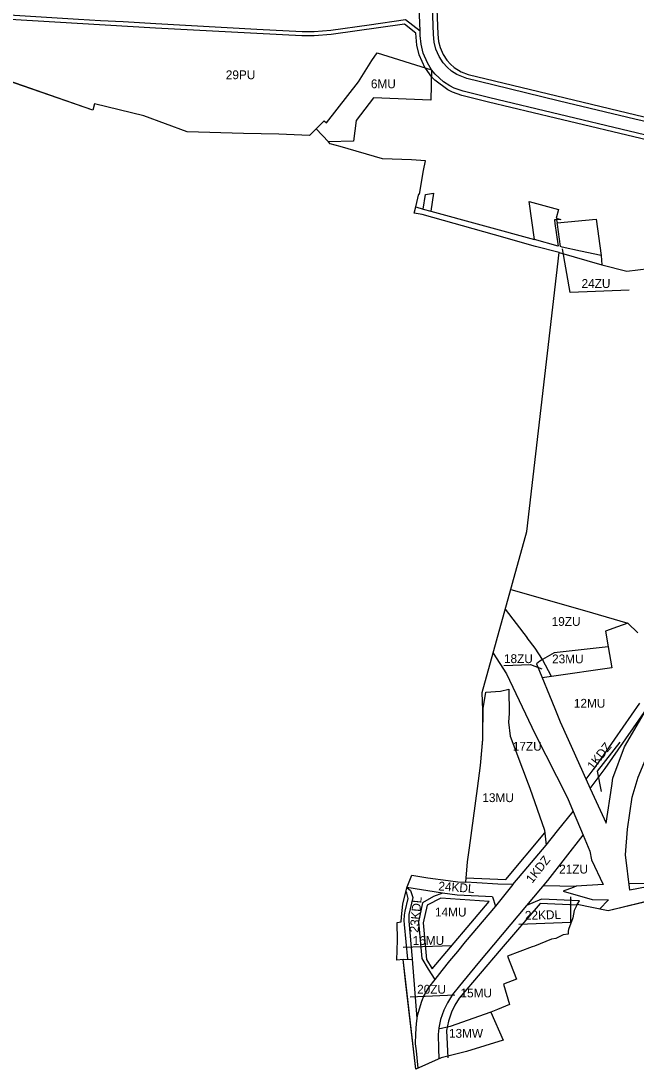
# Model space of a CAD drawing. Extents: x 7428203 to 7432868, y 5542672 to 5545406.
# Drawn here: x 7429895 to 7430591, y 5542672 to 5543859 of the extents above; entities that cross this region are included whole.
import ezdxf

# ---------------------------------------------------------------- set-up
doc = ezdxf.new("R2010")
doc.units = 0
for name, color, linetype in [('granica_planu', 7, 'Continuous'), ('linie_rozgraniczajace', 7, 'Continuous'), ('linie_zabudowy_nieprzekraczalne', 7, 'Continuous'), ('oznaczenia_przeznaczen', 7, 'Continuous')]:
    doc.layers.add(name, color=color, linetype=linetype)

msp = doc.modelspace()

# ---------------------------------------------------------------- linework, layer by layer
at = {"layer": 'granica_planu'}
for points in [[(7430399.26, 5542692.02), (7430370.61, 5542685.08), (7430341.91, 5542672.31), (7430330.7, 5542768.67), (7430330.7, 5542768.67), (7430327.49, 5542796.26), (7430320.3, 5542795.69), (7430321.05, 5542818.01), (7430320.88, 5542838.31), (7430325.25, 5542838.8), (7430325.66, 5542844.48), (7430327.19, 5542858.94), (7430328.79, 5542865.49), (7430332.01, 5542878.54), (7430337.22, 5542891.81), (7430355.36, 5542888.75), (7430378.35, 5542885.67), (7430389.37, 5542884.14), (7430398.44, 5542883.87), (7430400.23, 5542906.78), (7430402.42, 5542922.52), (7430411.79, 5542990), (7430415.17, 5543015.97), (7430417.67, 5543045.72), (7430417.86, 5543078.34), (7430416.94, 5543098.58), (7430467.52, 5543280.84), (7430504.08, 5543596.71), (7430477.25, 5543603.35), (7430430.7, 5543616.56), (7430348.97, 5543639.53), (7430340.06, 5543641.03), (7430341.69, 5543648.06), (7430345.12, 5543662.83), (7430346.18, 5543662.73), (7430350.57, 5543689.27), (7430352.87, 5543700.45), (7430336.88, 5543701.56), (7430304.26, 5543702.62), (7430256.11, 5543716.51), (7430245, 5543719.71), (7430243.12, 5543721.71), (7430229.11, 5543736.52), (7430221.53, 5543728.89), (7430186.76, 5543730.38), (7430146.86, 5543731.42), (7430083.21, 5543733.08), (7430033.89, 5543751.38), (7429978.34, 5543764.67), (7429976.28, 5543757.53), (7429864.43, 5543796.42)], [(7430647.46, 5542872.71), (7430559.44, 5542851.36), (7430524.39, 5542858.43), (7430520.91, 5542851.84), (7430519.38, 5542843.51), (7430514.61, 5542830.08), (7430514.44, 5542828.34), (7430514.29, 5542824.95), (7430508.52, 5542824.11), (7430500.18, 5542819.96), (7430495.44, 5542819.32), (7430476.16, 5542811.39), (7430473.47, 5542810.47), (7430445.63, 5542800.07), (7430455.63, 5542773.98), (7430441.2, 5542768.33), (7430447.71, 5542745.36), (7430434.45, 5542739.61), (7430426.73, 5542736.58), (7430440.59, 5542705.03), (7430399.26, 5542692.02)]]:
    msp.add_lwpolyline(points, dxfattribs=at)
at = {"layer": 'linie_rozgraniczajace'}
for p, q in [((7430361.88, 5543843.19), (7430359.23, 5543909.49)), ((7430346.91, 5543842.24), (7430346.69, 5543847.34)), ((7430347.76, 5543832.24), (7430346.91, 5543842.24)), ((7430362.6, 5543834.7), (7430361.88, 5543843.19)), ((7430350.31, 5543822), (7430347.76, 5543832.24)), ((7430364.56, 5543826.82), (7430362.6, 5543834.7)), ((7430368.19, 5543818.43), (7430364.56, 5543826.82)), ((7430276.96, 5543789.82), (7430292.1, 5543813.97)), ((7430292.1, 5543813.97), (7430298.18, 5543822.67)), ((7430298.18, 5543822.67), (7430359.58, 5543803.14)), ((7430354.93, 5543811.31), (7430350.31, 5543822)), ((7430372.8, 5543811.34), (7430368.19, 5543818.43)), ((7430359.58, 5543803.14), (7430354.93, 5543811.31)), ((7430359.58, 5543803.14), (7430358.92, 5543768.83)), ((7430363.63, 5543798.4), (7430359.58, 5543803.14)), ((7430377.38, 5543806.15), (7430372.8, 5543811.34)), ((7430382.32, 5543801.82), (7430377.38, 5543806.15)), ((7430388.18, 5543797.9), (7430382.32, 5543801.82)), ((7429976.28, 5543757.53), (7429864.43, 5543796.42)), ((7430240.89, 5543743.17), (7430276.96, 5543789.82)), ((7430373.17, 5543789.9), (7430363.63, 5543798.4)), ((7430380.46, 5543785.02), (7430373.17, 5543789.9)), ((7430399.68, 5543793.4), (7430388.18, 5543797.9)), ((7430429, 5543786.28), (7430399.68, 5543793.4)), ((7430385.17, 5543782.5), (7430380.46, 5543785.02)), ((7430395.48, 5543778.99), (7430385.17, 5543782.5)), ((7430425.46, 5543771.7), (7430395.48, 5543778.99)), ((7430504.48, 5543767.95), (7430429, 5543786.28)), ((7430293.83, 5543771.61), (7430274.43, 5543745.9)), ((7430358.92, 5543768.83), (7430293.83, 5543771.61)), ((7430583.41, 5543733.76), (7430425.46, 5543771.7)), ((7430589.68, 5543747.58), (7430504.48, 5543767.95)), ((7429978.34, 5543764.67), (7429976.28, 5543757.53)), ((7430033.89, 5543751.38), (7429978.34, 5543764.67)), ((7430083.21, 5543733.08), (7430033.89, 5543751.38)), ((7430229.11, 5543736.52), (7430238.02, 5543745.75)), ((7430238.02, 5543745.75), (7430240.89, 5543743.17)), ((7430274.43, 5543745.9), (7430271.19, 5543722.58)), ((7430715.18, 5543717.91), (7430589.68, 5543747.58)), ((7430146.86, 5543731.42), (7430083.21, 5543733.08)), ((7430186.76, 5543730.38), (7430146.86, 5543731.42)), ((7430221.53, 5543728.89), (7430186.76, 5543730.38)), ((7430229.11, 5543736.52), (7430221.53, 5543728.89)), ((7430243.12, 5543721.71), (7430229.11, 5543736.52)), ((7430710.02, 5543703.71), (7430583.41, 5543733.76)), ((7430271.19, 5543722.58), (7430243.12, 5543721.71)), ((7430245, 5543719.71), (7430243.12, 5543721.71)), ((7430256.11, 5543716.51), (7430245, 5543719.71)), ((7430304.26, 5543702.62), (7430256.11, 5543716.51)), ((7430336.88, 5543701.56), (7430304.26, 5543702.62)), ((7430352.87, 5543700.45), (7430336.88, 5543701.56)), ((7430350.57, 5543689.27), (7430352.87, 5543700.45)), ((7430346.18, 5543662.73), (7430350.57, 5543689.27)), ((7430341.69, 5543648.06), (7430345.12, 5543662.83)), ((7430345.12, 5543662.83), (7430346.18, 5543662.73)), ((7430340.06, 5543641.03), (7430341.69, 5543648.06)), ((7430341.69, 5543648.06), (7430350.15, 5543645.75)), ((7430476.18, 5543611.37), (7430470.01, 5543654.15)), ((7430470.01, 5543654.15), (7430503.27, 5543645.23)), ((7430348.97, 5543639.53), (7430340.06, 5543641.03)), ((7430430.7, 5543616.56), (7430348.97, 5543639.53)), ((7430350.15, 5543645.75), (7430358.87, 5543643.37)), ((7430358.87, 5543643.37), (7430476.18, 5543611.37)), ((7430503.27, 5543645.23), (7430500.82, 5543635.29)), ((7430500.82, 5543635.29), (7430505.8, 5543634)), ((7430505.8, 5543634), (7430501.2, 5543633.57)), ((7430501.2, 5543633.57), (7430501.96, 5543630.19)), ((7430501.96, 5543630.19), (7430545.85, 5543634.39)), ((7430545.85, 5543634.39), (7430551.46, 5543593.14)), ((7430477.25, 5543603.35), (7430430.7, 5543616.56)), ((7430504.08, 5543596.71), (7430477.25, 5543603.35)), ((7430467.52, 5543280.84), (7430504.08, 5543596.71)), ((7430504.08, 5543596.71), (7430552.28, 5543582.65)), ((7430551.46, 5543593.14), (7430552.28, 5543582.65)), ((7430580.6, 5543575.31), (7430686.19, 5543588.57)), ((7430552.28, 5543582.65), (7430580.6, 5543575.31)), ((7430416.94, 5543098.58), (7430467.52, 5543280.84)), ((7430449.28, 5543215.14), (7430532.69, 5543191.3)), ((7430443.12, 5543192.94), (7430467.68, 5543160.5)), ((7430569.97, 5543172.7), (7430556.39, 5543168.05)), ((7430581.89, 5543176.93), (7430569.97, 5543172.7)), ((7430556.39, 5543168.05), (7430559.49, 5543150.31)), ((7430559.53, 5543150.09), (7430498.37, 5543143.44)), ((7430429.27, 5543143.02), (7430444.56, 5543119.7)), ((7430498.37, 5543143.44), (7430485.23, 5543135.92)), ((7430482.22, 5543133.91), (7430478.48, 5543130.78)), ((7430478.48, 5543130.78), (7430499, 5543080.49)), ((7430485.23, 5543135.92), (7430482.22, 5543133.91)), ((7430495.56, 5543116.62), (7430485.26, 5543135.94)), ((7430444.56, 5543119.7), (7430476.37, 5543051.93)), ((7430495.53, 5543116.68), (7430484.82, 5543115.23)), ((7430417.86, 5543078.34), (7430416.94, 5543098.58)), ((7430417.69, 5543048.28), (7430417.86, 5543078.34)), ((7430499, 5543080.49), (7430505.15, 5543065.27)), ((7430505.15, 5543065.27), (7430514.17, 5543045.49)), ((7430415.17, 5543015.97), (7430417.63, 5543045.29)), ((7430448.69, 5543048.95), (7430469.17, 5542994.97)), ((7430476.37, 5543051.93), (7430513.64, 5542979.39)), ((7430514.17, 5543045.49), (7430539.24, 5542989.88)), ((7430411.79, 5542990), (7430415.17, 5543015.97)), ((7430402.42, 5542922.52), (7430411.79, 5542990)), ((7430513.64, 5542979.39), (7430520.07, 5542963.85)), ((7430520.07, 5542963.85), (7430531.21, 5542936.92)), ((7430487.47, 5542942.72), (7430489.31, 5542925.85)), ((7430400.23, 5542906.78), (7430402.42, 5542922.52)), ((7430398.44, 5542883.87), (7430400.23, 5542906.78)), ((7430332.01, 5542878.54), (7430337.22, 5542891.81)), ((7430337.22, 5542891.81), (7430355.36, 5542888.75)), ((7430355.36, 5542888.75), (7430378.35, 5542885.67)), ((7430328.79, 5542865.49), (7430332.01, 5542878.54)), ((7430378.35, 5542885.67), (7430389.37, 5542884.14)), ((7430389.37, 5542884.14), (7430398.44, 5542883.87)), ((7430410.98, 5542883.06), (7430398.44, 5542883.87)), ((7430434.66, 5542881.49), (7430410.98, 5542883.06)), ((7430451.8, 5542881.03), (7430431.89, 5542856.63)), ((7430451.8, 5542881.03), (7430434.66, 5542881.49)), ((7430486.43, 5542880.04), (7430523.21, 5542879.23)), ((7430327.19, 5542858.94), (7430328.79, 5542865.49)), ((7430361.86, 5542867.63), (7430349.22, 5542860.32)), ((7430372.11, 5542871.52), (7430361.86, 5542867.63)), ((7430388.67, 5542869.16), (7430372.11, 5542871.52)), ((7430428.81, 5542867.27), (7430388.67, 5542869.16)), ((7430527.12, 5542862.62), (7430483.9, 5542864.56)), ((7430647.46, 5542872.71), (7430559.44, 5542851.36)), ((7430325.66, 5542844.48), (7430327.19, 5542858.94)), ((7430349.22, 5542860.32), (7430345.03, 5542839.07)), ((7430524.39, 5542858.43), (7430520.91, 5542851.84)), ((7430524.39, 5542858.43), (7430527.12, 5542862.62)), ((7430559.44, 5542851.36), (7430524.39, 5542858.43)), ((7430325.25, 5542838.8), (7430325.66, 5542844.48)), ((7430519.38, 5542843.51), (7430514.61, 5542830.08)), ((7430520.91, 5542851.84), (7430519.38, 5542843.51)), ((7430320.88, 5542838.31), (7430325.25, 5542838.8)), ((7430321.05, 5542818.01), (7430320.88, 5542838.31)), ((7430345.03, 5542839.07), (7430348.61, 5542797.56)), ((7430514.61, 5542830.08), (7430514.44, 5542828.34)), ((7430320.3, 5542795.69), (7430321.05, 5542818.01)), ((7430495.44, 5542819.32), (7430476.16, 5542811.39)), ((7430500.18, 5542819.96), (7430495.44, 5542819.32)), ((7430508.52, 5542824.11), (7430500.18, 5542819.96)), ((7430514.29, 5542824.95), (7430508.52, 5542824.11)), ((7430514.44, 5542828.34), (7430514.29, 5542824.95)), ((7430473.47, 5542810.47), (7430445.63, 5542800.07)), ((7430476.16, 5542811.39), (7430473.47, 5542810.47)), ((7430327.49, 5542796.26), (7430320.3, 5542795.69)), ((7430327.49, 5542796.26), (7430337.69, 5542796.76)), ((7430330.47, 5542770.65), (7430327.49, 5542796.26)), ((7430337.69, 5542796.76), (7430342.98, 5542729.42)), ((7430348.61, 5542797.56), (7430355.92, 5542785.42)), ((7430445.63, 5542800.07), (7430455.63, 5542773.98)), ((7430355.92, 5542785.42), (7430363.19, 5542773.55)), ((7430341.91, 5542672.31), (7430330.47, 5542770.65)), ((7430455.63, 5542773.98), (7430441.2, 5542768.33)), ((7430441.2, 5542768.33), (7430447.71, 5542745.36)), ((7430434.45, 5542739.61), (7430426.73, 5542736.58)), ((7430426.73, 5542736.58), (7430440.59, 5542705.03)), ((7430447.71, 5542745.36), (7430434.45, 5542739.61)), ((7430440.59, 5542705.03), (7430399.26, 5542692.02)), ((7430342.34, 5542692.78), (7430344.11, 5542673.29)), ((7430367.45, 5542695.57), (7430368.03, 5542683.93)), ((7430399.26, 5542692.02), (7430370.61, 5542685.08)), ((7430370.61, 5542685.08), (7430341.91, 5542672.31))]:
    msp.add_line(p, q, dxfattribs=at)
for points in [[(7429692.68, 5543891.06), (7429733.68, 5543881.76), (7429787.12, 5543873.02), (7429851.1, 5543867.29), (7429960.09, 5543860.73), (7429984.9, 5543859.31), (7430010.49, 5543857.85), (7430047.45, 5543855.75), (7430162.05, 5543849.26), (7430213.06, 5543846.63), (7430226.75, 5543846.71), (7430245.5, 5543848.19), (7430288.91, 5543854.44), (7430330.3, 5543860.39), (7430346.69, 5543847.34), (7430344.79, 5543892.69)], [(7430350.15, 5543645.75), (7430352.89, 5543662.25), (7430361.91, 5543663.73), (7430358.87, 5543643.37)], [(7430501.2, 5543633.57), (7430498.67, 5543633.41), (7430498.99, 5543629.46), (7430502.95, 5543603.85), (7430476.18, 5543611.37)], [(7430551.46, 5543593.14), (7430528.07, 5543598.17), (7430507.44, 5543602.61), (7430505.43, 5543603.17), (7430502.22, 5543628.07), (7430501.96, 5543630.19)], [(7430532.69, 5543191.3), (7430581.89, 5543176.93), (7430593.17, 5543166.03)], [(7430485.23, 5543135.92), (7430477.03, 5543148.51), (7430467.68, 5543160.5)], [(7430559.49, 5543150.31), (7430563.82, 5543126.34), (7430495.56, 5543116.62)], [(7430417.63, 5543045.29), (7430417.69, 5543048.28), (7430418.24, 5543080.69), (7430419.99, 5543091.55), (7430421.2, 5543099.06), (7430437.63, 5543100.02), (7430447.03, 5543102.19), (7430447.64, 5543074.71)], [(7430539.24, 5542989.88), (7430556.31, 5543012.63), (7430602.9, 5543079.56)], [(7430539.24, 5542989.88), (7430557.16, 5542950.48), (7430563.6, 5542992.83), (7430564.95, 5543001.72), (7430577.95, 5543036.88), (7430602.9, 5543079.56)], [(7430447.64, 5543074.71), (7430446.92, 5543064.79), (7430448.69, 5543048.95)], [(7430469.17, 5542994.97), (7430470.88, 5542990.09), (7430487.47, 5542942.72)], [(7430489.31, 5542925.85), (7430502.35, 5542941.84), (7430520.07, 5542963.85)], [(7430467.32, 5542857.57), (7430491.32, 5542885.79), (7430531.21, 5542936.92)], [(7430531.21, 5542936.92), (7430538.6, 5542919.04), (7430540.81, 5542909.2), (7430553.97, 5542881.23), (7430523.21, 5542879.23), (7430519.92, 5542877.98), (7430508.59, 5542873.68), (7430541.48, 5542864.32), (7430560.09, 5542863.73), (7430549.55, 5542853.35)], [(7430451.8, 5542881.03), (7430468.8, 5542901.34), (7430489.31, 5542925.85)], [(7430331.83, 5542877.83), (7430335.81, 5542874.22), (7430338.62, 5542866.39), (7430333.86, 5542847.22), (7430333.76, 5542839.74), (7430337.67, 5542797.06), (7430337.69, 5542796.76)], [(7430372.11, 5542871.52), (7430331.85, 5542877.9)], [(7430428.81, 5542867.27), (7430431.89, 5542856.63), (7430397.61, 5542816.45), (7430388.85, 5542805.53), (7430380.09, 5542794.61), (7430371.33, 5542783.69), (7430363.19, 5542773.55), (7430356.1, 5542764.43), (7430350.79, 5542755.39), (7430348.29, 5542748.82), (7430343.44, 5542732.52), (7430342.17, 5542723.94), (7430341.3, 5542712.14), (7430341.24, 5542700.97), (7430342.34, 5542692.78)], [(7430483.9, 5542864.56), (7430467.23, 5542857.54), (7430411.85, 5542791.89), (7430391.22, 5542766.38), (7430383.31, 5542756.6), (7430377.71, 5542747.31), (7430373.52, 5542738.97), (7430369.8, 5542728.5), (7430367.81, 5542718.82), (7430366.96, 5542711.48), (7430367.45, 5542695.57)], [(7430426.73, 5542736.58), (7430380.78, 5542720.64), (7430367.64, 5542717.38)]]:
    msp.add_lwpolyline(points, dxfattribs=at)
msp.add_lwpolyline([(7430802.24, 5542918.55), (7430613.59, 5542879.57), (7430603.73, 5542878.38), (7430583.89, 5542874.93), (7430579.15, 5542914.59), (7430581.28, 5542943.83), (7430586.64, 5542980.02), (7430593.65, 5543002.63), (7430602.22, 5543023.27), (7430618.72, 5543051.98), (7430623.29, 5543059.94), (7430640.04, 5543078.8), (7430655.04, 5543090.28), (7430667.34, 5543085.03), (7430803.34, 5542928.16)], close=True, dxfattribs=at)
at = {"layer": 'linie_zabudowy_nieprzekraczalne'}
for p, q in [((7430443.57, 5542886.77), (7430487.74, 5542939.56)), ((7430398.44, 5542888.89), (7430443.57, 5542886.77)), ((7430424.75, 5542862.06), (7430370.01, 5542865.54)), ((7430360.34, 5542785.8), (7430424.75, 5542862.06))]:
    msp.add_line(p, q, dxfattribs=at)
for points in [[(7430364.22, 5543909.88), (7430366.87, 5543843.51), (7430367.55, 5543835.53), (7430369.32, 5543828.42), (7430372.62, 5543820.8), (7430376.79, 5543814.37), (7430380.91, 5543809.7), (7430385.37, 5543805.8), (7430393.16, 5543800.91), (7430401.08, 5543798.21), (7430590.92, 5543752.42), (7430800.06, 5543702.97), (7430877.17, 5543684.2), (7430886.57, 5543682.45), (7430893.51, 5543682.18), (7430916.89, 5543684.34), (7430970.59, 5543689.23), (7431085, 5543701.71), (7431096.64, 5543746.01), (7431141.07, 5543916.56)], [(7430352.56, 5543805.37), (7430345.56, 5543820.39), (7430342.81, 5543831.42), (7430341.79, 5543844.85), (7430328.95, 5543855.08), (7430246.14, 5543843.23), (7430226.91, 5543841.71), (7430212.94, 5543841.63), (7430161.78, 5543844.27), (7430047.23, 5543850.54), (7429850.78, 5543862.3), (7429817.78, 5543864.62), (7429787.47, 5543867.62), (7429750.04, 5543873.61), (7429700.15, 5543884.05)], [(7431065.36, 5543628.41), (7431071.52, 5543651.7), (7431064.4, 5543654.82), (7431057.52, 5543662.55), (7431053.97, 5543671.8), (7431053.88, 5543673.17), (7430976.83, 5543664.76), (7430904.37, 5543658.08), (7430893.94, 5543657.12), (7430886.66, 5543657.24), (7430878.99, 5543658.2), (7430832.69, 5543669.56), (7430708.87, 5543698.85), (7430499.81, 5543748.5), (7430424.28, 5543766.84), (7430394.08, 5543774.18), (7430383.18, 5543777.9), (7430377.88, 5543780.73), (7430363.42, 5543791.79), (7430360.03, 5543794.93), (7430352.73, 5543805.17)], [(7430534.59, 5543000.35), (7430548.21, 5543018.49), (7430595.53, 5543086.32)], [(7430582.67, 5542882.44), (7430604.39, 5542882.87), (7430646.89, 5542890.7), (7430761.21, 5542915.18), (7430797.42, 5542922.66), (7430798.11, 5542926.47), (7430768.53, 5542960.68), (7430729.57, 5543005.62), (7430675.05, 5543068.5), (7430662.1, 5543083.43)], [(7430332.86, 5542796.52), (7430329.08, 5542836.03), (7430328.48, 5542840.28), (7430328.85, 5542846.32), (7430329.6, 5542850.84), (7430333.19, 5542865.26), (7430331.52, 5542871.38), (7430330.74, 5542873.41)], [(7430370.01, 5542865.54), (7430354.8, 5542857.77), (7430350.15, 5542837.9), (7430353.98, 5542796.37), (7430360.34, 5542785.8)], [(7430524.5, 5542857.76), (7430482.57, 5542859.76), (7430438.48, 5542808.4), (7430391.01, 5542752.35), (7430386.05, 5542744.66), (7430382.1, 5542736.58), (7430378.64, 5542726.43), (7430376.61, 5542715.86), (7430377.99, 5542684.83)]]:
    msp.add_lwpolyline(points, dxfattribs=at)
at = {"layer": 'oznaczenia_przeznaczen'}
for p, q in [((7430327.58, 5542810.08), (7430382.7, 5542812.31)), ((7430335.42, 5542754.13), (7430385.88, 5542756.18))]:
    msp.add_line(p, q, dxfattribs=at)
for points in [[(7430583.43, 5543554.04), (7430516.36, 5543551.32), (7430507.94, 5543600.65)], [(7430441.34, 5543129.16), (7430471.66, 5543130.39), (7430484.54, 5543125.27)], [(7430572.86, 5543042.35), (7430547.15, 5543009.34), (7430551.5, 5542986.61)], [(7430458.46, 5542836.13), (7430517.17, 5542838.51), (7430517.43, 5542867.38)]]:
    msp.add_lwpolyline(points, dxfattribs=at)

# ---------------------------------------------------------------- texts
for s, p in [('29PU', (7430126.7528, 5543792.7)), ('6MU', (7430290.9864, 5543782.49)), ('24ZU', (7430529.3928, 5543556.41)), ('19ZU', (7430495.5628, 5543173.93)), ('18ZU', (7430441.5728, 5543131.81)), ('23MU', (7430496.0432, 5543131.51)), ('12MU', (7430520.6732, 5543081.29)), ('17ZU', (7430451.6328, 5543032.64)), ('13MU', (7430417.1132, 5542974.47)), ('21ZU', (7430504.0328, 5542893.6)), ('14MU', (7430363.5032, 5542844.97)), ('16MU', (7430338.2332, 5542812.78)), ('20ZU', (7430343.3128, 5542757.61)), ('15MU', (7430392.3932, 5542753.42)), ('13MW', (7430379.3237, 5542707.7))]:
    msp.add_text(s, height=10, dxfattribs=at).set_placement(p)
for s, rotation, p in [('1KDZ', 51.8677379, (7430542.726, 5543010.0101)), ('1KDZ', 51.8446255, (7430473.5182, 5542881.8237)), ('24KDL', 355.781212, (7430367.1104, 5542874.5511)), ('23KDL', 84.5310525, (7430344.6995, 5542826.3346)), ('22KDL', 1.5505021, (7430465.4415, 5542841.1739))]:
    msp.add_text(s, height=10, rotation=rotation, dxfattribs=at).set_placement(p)

doc.saveas('drawing.dxf')
